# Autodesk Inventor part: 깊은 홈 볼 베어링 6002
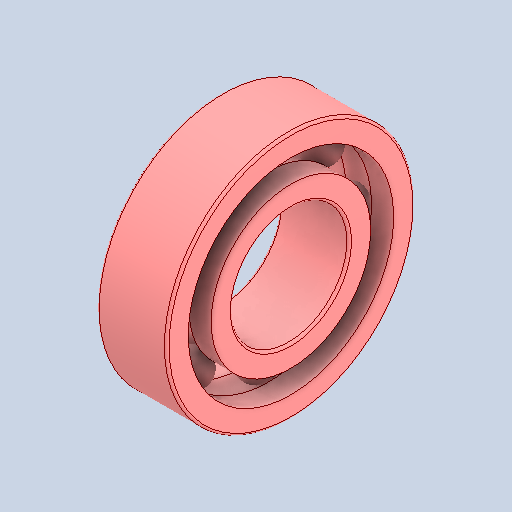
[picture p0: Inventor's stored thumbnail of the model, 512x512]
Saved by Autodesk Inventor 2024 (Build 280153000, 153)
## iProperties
Created: 2025-10
Part Number: 깊은 홈 볼 베어링 6002
Material: 강철, 연강
Description: 깊은 그루브 볼 베어링
Document SubType Name: Modeling
Designer: EDU03
Density: 7.85 g/cm^3
Appearance: 기본값
Author: jhkim
Sending System: Autodesk Inventor 2026
Preprocessor: ST-DEVELOPER v20.1
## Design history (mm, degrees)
feature "Solid1"
feature "Solid1:1"
feature "Solid1:2"
feature "Solid1:3"
feature "Solid1:4"
feature "Solid1:5"
feature "Solid1:6"
feature "Solid1:7"
feature "Solid1:8"
feature "Solid1:9"
node "솔리드1"
node "솔리드2"
node "솔리드3"
node "솔리드4"
node "솔리드5"
node "솔리드6"
node "솔리드7"
node "솔리드8"
node "솔리드9"
node "솔리드10"
